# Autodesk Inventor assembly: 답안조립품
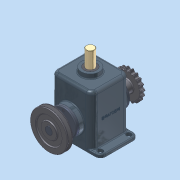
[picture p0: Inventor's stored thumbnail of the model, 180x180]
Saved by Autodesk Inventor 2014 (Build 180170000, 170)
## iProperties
Created: 2015-01
Part Number: 답안조립품
Document SubType Name: Assembly
Designer: net
Mass: 8617.99 g
Surface Area: 4424.11 cm^2
Volume: 1987.45 cm^3
Density: 4.33619 g/cm^3
Author: net
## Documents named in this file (15)
- C:\Users\net\Desktop\350105V1005\답안조립품.iam
- C:\Users\net\Desktop\350105V1005\본체.ipt
- C:\Users\net\Desktop\350105V1005\M4x0.5.ipt
- C:\Users\net\Desktop\350105V1005\V-벨트풀리.ipt
- C:\Users\net\Desktop\350105V1005\멈춤나사 M5x0.5.ipt
- C:\Users\net\Desktop\350105V1005\멈춤링.ipt
- C:\Users\net\Desktop\350105V1005\베어링 6205.ipt
- C:\Users\net\Desktop\350105V1005\부시.ipt
- C:\Users\net\Desktop\350105V1005\슬라이드.ipt
- C:\Users\net\Desktop\350105V1005\오일실.ipt
- C:\Users\net\Desktop\350105V1005\체인 스프로킷.ipt
- C:\Users\net\Desktop\350105V1005\커버.ipt
- C:\Users\net\Desktop\350105V1005\키 8x8.ipt
- C:\Users\net\Desktop\350105V1005\편심축.ipt
- C:\Users\net\Desktop\350105V1005\스프링.ipt
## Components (8 placed, 3 different names)
1. V-벨트풀리:1
2. 5-체인 스프로킷:1
3. M4x0.5:1
4. M4x0.5:3
5. M4x0.5:4
6. M4x0.5:2
7. M4x0.5:5
8. M4x0.5:6
